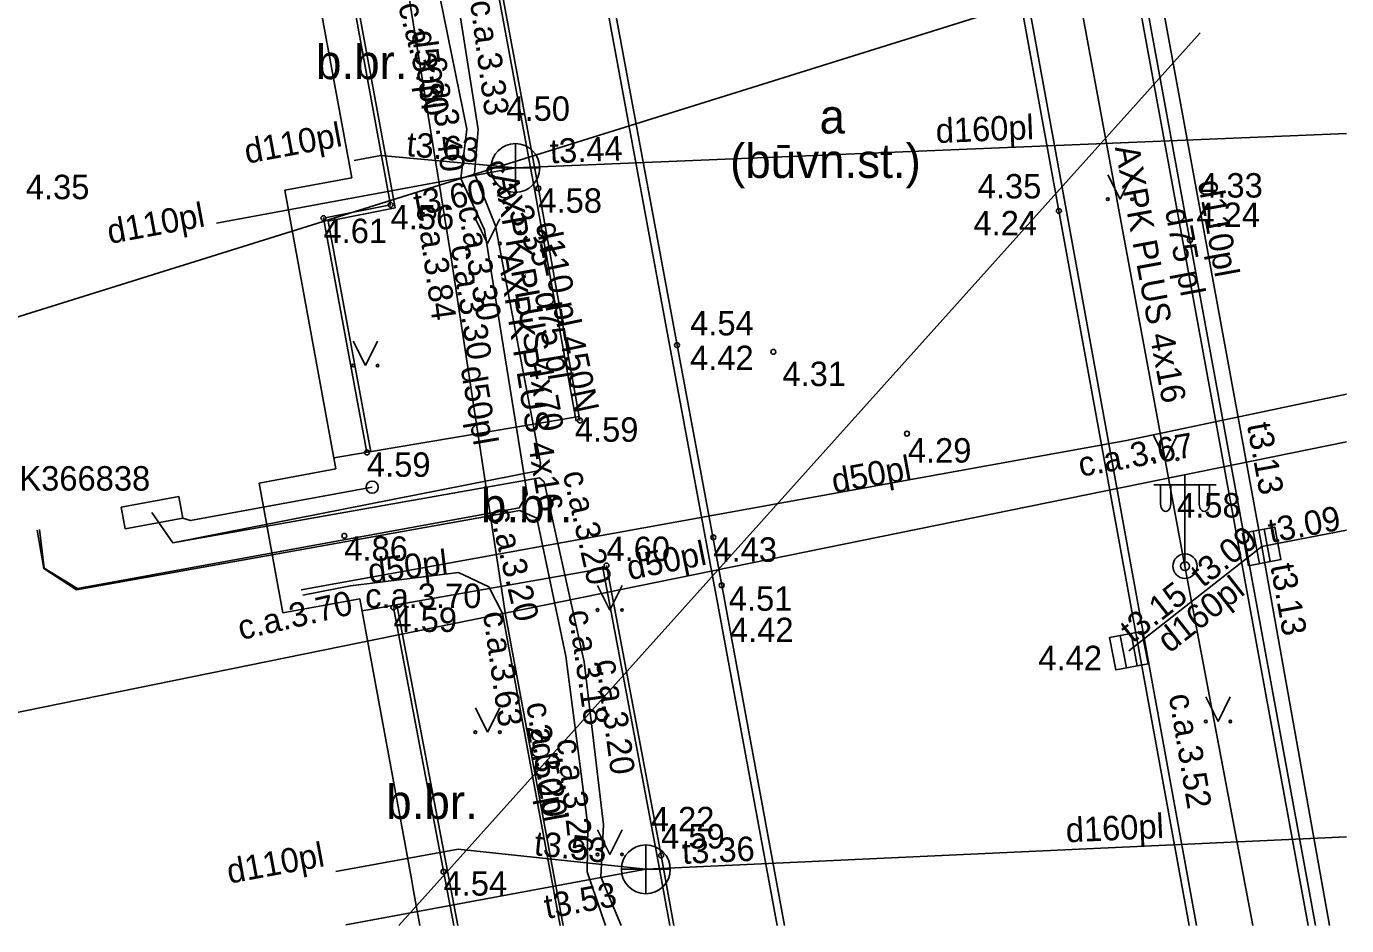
# Model space of a CAD drawing. Extents: x 484635 to 484808, y 278866 to 278977.
# Drawn here: x 484780.57 to 484807.57, y 278866.04 to 278884.44 of the extents above; entities that cross this region are included whole.
import ezdxf

# ---------------------------------------------------------------- set-up
doc = ezdxf.new("R2010")
doc.units = 0
for name, color, linetype in [('APGS_ACRL_####_####_#', 7, 'Continuous'), ('APGS_ACRL_####_TKST_#', 7, 'Continuous'), ('APGS_ELEM_####_####_#', 7, 'Continuous'), ('APGS_ELEM_####_TKST_#', 7, 'Continuous'), ('APGS_VADP_ZSPR_####_I', 7, 'Continuous'), ('APGS_VADP_ZSPR_TKST_I', 7, 'Continuous'), ('BUVE_EKAS_####_####_#', 7, 'Continuous'), ('CELI_CAPM_####_####_#', 7, 'Continuous'), ('CELI_CMAL_####_####_#', 7, 'Continuous'), ('CELI_CSEG_####_TKST_#', 7, 'Continuous'), ('CKOM_ELEM_####_####_#', 7, 'Continuous'), ('CKOM_ZEMJ_####_####_#', 7, 'Continuous'), ('DREN_VADP_####_####_I', 7, 'Continuous'), ('DREN_VADP_####_TKST_I', 7, 'Continuous'), ('ELEK_ACRL_####_####_#', 7, 'Continuous'), ('ELEK_ACRL_####_TKST_#', 7, 'Continuous'), ('ELEK_ELEM_####_####_#', 7, 'Continuous'), ('ELEK_ELEM_####_TKST_#', 7, 'Continuous'), ('ELEK_VADP_ZSPR_####_I', 7, 'Continuous'), ('ELEK_VADP_ZSPR_TKST_I', 7, 'Continuous'), ('LKAN_ELEM_####_####_#', 7, 'Continuous'), ('LKAN_ELEM_PAST_TKST_#', 7, 'Continuous'), ('LKAN_VADP_PAST_####_I', 7, 'Continuous'), ('LKAN_VADP_PAST_TKST_I', 7, 'Continuous'), ('RELJ_AATZ_####_TKST_#', 7, 'Continuous'), ('RELJ_ELEM_####_####_#', 7, 'Continuous'), ('SAKK_KKAN_####_####_I', 7, 'Continuous'), ('SAKK_KKAN_####_TKST_I', 7, 'Continuous'), ('SAKT_VADP_NEDR_####_#', 7, 'Continuous'), ('SKAN_ELEM_####_####_#', 7, 'Continuous'), ('SKAN_ELEM_PAST_TKST_#', 7, 'Continuous'), ('SKAN_VADP_NEDR_####_#', 7, 'Continuous'), ('SKAN_VADP_PAST_####_I', 7, 'Continuous'), ('SKAN_VADP_PAST_TKST_I', 7, 'Continuous'), ('TERT_ELEM_####_####_#', 7, 'Continuous'), ('UDTK_VADP_UDEN_####_I', 7, 'Continuous'), ('UDTK_VADP_UDEN_TKST_I', 7, 'Continuous')]:
    doc.layers.add(name, color=color, linetype=linetype)

msp = doc.modelspace()

# ---------------------------------------------------------------- linework, layer by layer
at = {"layer": 'APGS_ACRL_####_####_#'}
msp.add_lwpolyline([(484800.949, 278891.291), (484804.267, 278873.397), (484805.658, 278866.043)], dxfattribs=at)
at = {"layer": 'APGS_ELEM_####_####_#'}
for p, q in [((484804.267, 278873.397), (484804.267, 278875.28)), ((484804.267, 278875.064), (484803.632, 278875.059)), ((484803.767, 278875.06), (484803.767, 278874.668)), ((484803.977, 278875.062), (484803.977, 278874.668)), ((484804.267, 278875.064), (484804.902, 278875.059)), ((484804.557, 278875.062), (484804.557, 278874.668)), ((484804.767, 278875.06), (484804.767, 278874.668))]:
    msp.add_line(p, q, dxfattribs=at)
for radius in [0.25, 0.09]:
    msp.add_circle((484804.267, 278873.397), radius, dxfattribs=at)
for centre, major_axis, start_param, end_param in [((484803.872, 278874.668), (0, 0.151), 1.570796, 4.712389), ((484804.662, 278874.668), (0, -0.151), 4.712389, 7.853982)]:
    msp.add_ellipse(centre, major_axis=major_axis, ratio=0.695971, start_param=start_param, end_param=end_param, dxfattribs=at)
at = {"layer": 'APGS_VADP_ZSPR_####_I'}
msp.add_lwpolyline([(484800.949, 278891.291), (484804.267, 278873.397), (484805.658, 278866.043)], dxfattribs=at)
at = {"layer": 'BUVE_EKAS_####_####_#'}
for p, q in [((484787.226, 278881.344), (484786.113, 278887.392)), ((484785.849, 278881.09), (484787.226, 278881.344)), ((484785.849, 278881.09), (484786.898, 278875.386)), ((484785.325, 278875.097), (484786.898, 278875.386)), ((484785.813, 278872.441), (484785.325, 278875.097)), ((484787.387, 278872.731), (484785.813, 278872.441)), ((484787.387, 278872.731), (484788.441, 278867.002)), ((484788.486, 278866.756), (484788.441, 278867.002)), ((484788.486, 278866.756), (484788.617, 278866.043))]:
    msp.add_line(p, q, dxfattribs=at)
at = {"layer": 'CELI_CAPM_####_####_#'}
for p, q in [((484793.728, 278877.892), (484792.044, 278886.997)), ((484793.875, 278877.919), (484792.191, 278887.024)), ((484794.641, 278872.977), (484793.728, 278877.891)), ((484794.789, 278873.005), (484793.875, 278877.919)), ((484796.077, 278866.043), (484794.789, 278873.005)), ((484795.925, 278866.043), (484794.641, 278872.978))]:
    msp.add_line(p, q, dxfattribs=at)
for points in [[(484806.787, 278866.043), (484804.221, 278880.039), (484801.029, 278897.438)], [(484806.939, 278866.043), (484804.369, 278880.066), (484801.177, 278897.465)], [(484798.696, 278897.09), (484801.688, 278880.665), (484804.352, 278866.043)], [(484798.844, 278897.117), (484801.835, 278880.691), (484804.505, 278866.043)], [(484789.731, 278887.748), (484790.96, 278881.112), (484791.811, 278876.364)], [(484789.809, 278887.762), (484791.039, 278881.126), (484791.89, 278876.378)], [(484786.839, 278887.208), (484788.016, 278880.789), (484786.643, 278880.516), (484787.532, 278875.724)], [(484786.919, 278887.216), (484788.109, 278880.725), (484786.736, 278880.453), (484787.611, 278875.738)], [(484792.353, 278873.395), (484793.472, 278867.462), (484793.727, 278866.043)], [(484792.432, 278873.41), (484793.55, 278867.477), (484793.808, 278866.043)], [(484789.308, 278866.043), (484788.074, 278872.551)], [(484789.389, 278866.043), (484788.144, 278872.607)]]:
    msp.add_lwpolyline(points, dxfattribs=at)
at = {"layer": 'CELI_CMAL_####_####_#'}
for points in [[(484786.857, 278875.612), (484791.875, 278876.458)], [(484787.433, 278872.482), (484792.441, 278873.362)]]:
    msp.add_lwpolyline(points, dxfattribs=at)
at = {"layer": 'CKOM_ELEM_####_####_#'}
msp.add_circle((484787.638, 278875.013), 0.125, dxfattribs=at)
at = {"layer": 'CKOM_ZEMJ_####_####_#'}
msp.add_lwpolyline([(484783.763, 278874.38), (484783.925, 278874.33), (484787.638, 278875.013)], dxfattribs=at)
at = {"layer": 'DREN_VADP_####_####_I'}
for points in [[(484805.836, 278873.802), (484802.968, 278889.456)], [(484807.226, 278866.043), (484805.836, 278873.802)]]:
    msp.add_lwpolyline(points, dxfattribs=at)
at = {"layer": 'ELEK_ACRL_####_####_#'}
for points in [[(484782.967, 278889.326), (484783.337, 278888.722), (484788.452, 278889.478), (484789.367, 278885.14), (484789.804, 278882.334), (484789.731, 278881.43), (484790.16, 278880.357), (484791.085, 278875.503), (484791.062, 278875.354), (484783.559, 278873.877), (484783.132, 278874.493)], [(484781.185, 278888.845), (484781.329, 278888.091), (484781.841, 278887.878), (484786.673, 278888.772), (484788.257, 278888.812), (484789.576, 278882.339), (484789.452, 278881.33), (484789.936, 278880.279), (484790.808, 278874.869), (484790.648, 278874.587), (484781.611, 278872.941), (484780.931, 278873.356), (484780.833, 278874.148)], [(484783.132, 278874.493), (484783.559, 278873.877), (484791.062, 278875.206), (484791.16, 278875.122), (484791.974, 278871.437), (484792.371, 278868.102), (484792.32, 278867.041), (484792.736, 278866.043)], [(484780.786, 278874.134), (484780.92, 278873.348), (484781.587, 278872.91), (484790.66, 278874.534), (484791.005, 278874.377), (484791.603, 278871.553), (484792.054, 278868.088), (484792.037, 278867.141), (484792.413, 278866.043)]]:
    msp.add_lwpolyline(points, dxfattribs=at)
at = {"layer": 'ELEK_ELEM_####_####_#'}
msp.add_lwpolyline([(484782.502, 278874.606), (484783.682, 278874.822), (484783.763, 278874.38), (484782.583, 278874.163)], close=True, dxfattribs=at)
at = {"layer": 'ELEK_VADP_ZSPR_####_I'}
for points in [[(484782.967, 278889.326), (484783.337, 278888.722), (484788.452, 278889.478), (484789.367, 278885.14), (484789.804, 278882.334), (484789.731, 278881.43), (484790.16, 278880.357), (484791.085, 278875.503), (484791.062, 278875.354), (484783.559, 278873.877), (484783.132, 278874.493)], [(484781.185, 278888.845), (484781.329, 278888.091), (484781.841, 278887.878), (484786.673, 278888.772), (484788.257, 278888.812), (484789.576, 278882.339), (484789.452, 278881.33), (484789.936, 278880.279), (484790.808, 278874.869), (484790.648, 278874.587), (484781.611, 278872.941), (484780.931, 278873.356), (484780.833, 278874.148)], [(484783.132, 278874.493), (484783.559, 278873.877), (484791.062, 278875.206), (484791.16, 278875.122), (484791.974, 278871.437), (484792.371, 278868.102), (484792.32, 278867.041), (484792.736, 278866.043)], [(484780.786, 278874.134), (484780.92, 278873.348), (484781.587, 278872.91), (484790.66, 278874.534), (484791.005, 278874.377), (484791.603, 278871.553), (484792.054, 278868.088), (484792.037, 278867.141), (484792.413, 278866.043)]]:
    msp.add_lwpolyline(points, dxfattribs=at)
at = {"layer": 'LKAN_ELEM_####_####_#'}
for p, q in [((484805.663, 278874.112), (484805.789, 278873.449)), ((484805.884, 278874.155), (484806.01, 278873.491)), ((484802.944, 278871.978), (484803.07, 278871.315)), ((484803.165, 278872.02), (484803.291, 278871.357))]:
    msp.add_line(p, q, dxfattribs=at)
for points in [[(484805.442, 278874.07), (484806.105, 278874.197), (484806.231, 278873.533), (484805.568, 278873.407)], [(484802.723, 278871.936), (484803.386, 278872.062), (484803.512, 278871.399), (484802.849, 278871.273)]]:
    msp.add_lwpolyline(points, close=True, dxfattribs=at)
at = {"layer": 'LKAN_VADP_PAST_####_I'}
for points in [[(484805.836, 278873.802), (484807.573, 278874.132)], [(484803.117, 278871.667), (484805.836, 278873.802)]]:
    msp.add_lwpolyline(points, dxfattribs=at)
at = {"layer": 'RELJ_ELEM_####_####_#'}
for centre in [(484791.039, 278881.126), (484788.016, 278880.789), (484786.643, 278880.516), (484801.688, 278880.665), (484804.369, 278880.066), (484793.875, 278877.919), (484795.846, 278877.781), (484791.89, 278876.378), (484798.579, 278876.108), (484787.532, 278875.724), (484787.069, 278874.017), (484794.619, 278873.986), (484792.432, 278873.41), (484794.789, 278873.005), (484788.074, 278872.551), (484793.55, 278867.477), (484789.099, 278867.147)]:
    msp.add_circle(centre, 0.05, dxfattribs=at)
at = {"layer": 'SAKK_KKAN_####_####_I'}
for points in [[(484784.69, 278887.431), (484786.281, 278887.759), (484787.215, 278887.727), (484787.779, 278887.388), (484788.143, 278886.589), (484789.238, 278879.793), (484790.369, 278872.4), (484791.546, 278866.043)], [(484807.573, 278876.913), (484803.072, 278875.969), (484786.187, 278872.916)], [(484786.222, 278872.805), (484787.195, 278872.997), (484789.405, 278873.268), (484790.029, 278872.975), (484790.303, 278872.431), (484791.483, 278866.043)]]:
    msp.add_lwpolyline(points, dxfattribs=at)
at = {"layer": 'SAKT_VADP_NEDR_####_#'}
msp.add_line((484788.185, 278866.043), (484804.576, 278884.31), dxfattribs=at)
at = {"layer": 'SKAN_ELEM_####_####_#'}
for p, q in [((484790.568, 278881.044), (484790.568, 278882.044)), ((484790.068, 278881.544), (484791.068, 278881.544)), ((484793.237, 278866.695), (484793.237, 278867.695)), ((484792.737, 278867.195), (484793.737, 278867.195))]:
    msp.add_line(p, q, dxfattribs=at)
for centre in [(484790.568, 278881.544), (484793.237, 278867.195)]:
    msp.add_circle(centre, 0.5, dxfattribs=at)
at = {"layer": 'SKAN_VADP_NEDR_####_#'}
msp.add_lwpolyline([(484756.132, 278870.921), (484807.573, 278886.997)], dxfattribs=at)
at = {"layer": 'SKAN_VADP_PAST_####_I'}
for p, q in [((484784.455, 278880.413), (484790.568, 278881.544)), ((484786.898, 278867.149), (484789.396, 278867.61)), ((484789.396, 278867.61), (484793.237, 278867.195)), ((484787.099, 278866.056), (484793.237, 278867.195))]:
    msp.add_line(p, q, dxfattribs=at)
for points in [[(484790.568, 278881.544), (484807.573, 278882.25)], [(484790.568, 278881.544), (484787.815, 278881.799), (484787.268, 278881.698)], [(484793.237, 278867.195), (484807.573, 278867.859)]]:
    msp.add_lwpolyline(points, dxfattribs=at)
at = {"layer": 'TERT_ELEM_####_####_#'}
for p, q in [((484802.688, 278881.403), (484802.938, 278880.903)), ((484802.938, 278880.903), (484803.188, 278881.403)), ((484789.75, 278880.5), (484790, 278880)), ((484790, 278880), (484790.25, 278880.5)), ((484787.25, 278878), (484787.5, 278877.5)), ((484787.5, 278877.5), (484787.75, 278878)), ((484803.616, 278876.086), (484803.866, 278875.586)), ((484803.866, 278875.586), (484804.116, 278876.086)), ((484792.25, 278873), (484792.5, 278872.5)), ((484792.5, 278872.5), (484792.75, 278873)), ((484804.694, 278870.721), (484804.944, 278870.221)), ((484804.944, 278870.221), (484805.194, 278870.721)), ((484789.75, 278870.5), (484790, 278870)), ((484790, 278870), (484790.25, 278870.5)), ((484792.25, 278868), (484792.5, 278867.5)), ((484792.5, 278867.5), (484792.75, 278868))]:
    msp.add_line(p, q, dxfattribs=at)
for centre, radius in [((484802.688, 278880.903), 0.028), ((484803.188, 278880.903), 0.0263), ((484789.75, 278880), 0.028), ((484790.25, 278880), 0.0263), ((484787.25, 278877.5), 0.028), ((484787.75, 278877.5), 0.0263), ((484803.615, 278875.585), 0.028), ((484804.115, 278875.585), 0.0263), ((484792.25, 278872.5), 0.028), ((484792.75, 278872.5), 0.0263), ((484789.75, 278870), 0.028), ((484790.25, 278870), 0.0263), ((484804.694, 278870.22), 0.028), ((484805.194, 278870.22), 0.0263), ((484792.25, 278867.5), 0.028), ((484792.75, 278867.5), 0.0263)]:
    msp.add_circle(centre, radius, dxfattribs=at)
at = {"layer": 'UDTK_VADP_UDEN_####_I'}
msp.add_lwpolyline([(484807.573, 278875.943), (484775.943, 278869.5)], dxfattribs=at)

# ---------------------------------------------------------------- texts
at = {"layer": 'APGS_ACRL_####_TKST_#'}
msp.add_text('d75 pl', height=0.5, rotation=280.5048, dxfattribs=at).set_placement((484803.858, 278880.682))
at = {"layer": 'APGS_ELEM_####_TKST_#'}
msp.add_text('c.a.3.52', height=0.5, rotation=279.4578, dxfattribs=at).set_placement((484803.934, 278870.751))
at = {"layer": 'APGS_VADP_ZSPR_TKST_I'}
msp.add_text('AXPK PLUS 4x16', height=0.5, rotation=280.5048, dxfattribs=at).set_placement((484802.831, 278881.965))
at = {"layer": 'CELI_CSEG_####_TKST_#'}
for s, p in [('b.br.', (484786.49, 278883.361)), ('a', (484796.791, 278882.249)), ('(būvn.st.)', (484794.961, 278881.339)), ('b.br.', (484789.864, 278874.291)), ('b.br.', (484787.927, 278868.224))]:
    msp.add_text(s, height=0.7, dxfattribs=at).set_placement(p)
at = {"layer": 'DREN_VADP_####_TKST_I'}
for s, rotation, p in [('d110pl', 280.3837, (484804.528, 278881.257)), ('t3.13', 280.3837, (484805.533, 278876.289)), ('t3.13', 280.1533, (484806.013, 278873.406))]:
    msp.add_text(s, height=0.5, rotation=rotation, dxfattribs=at).set_placement(p)
at = {"layer": 'ELEK_ACRL_####_TKST_#'}
for s, rotation, p in [('c.a.3.30', 284.2745, (484788.165, 278884.87)), ('c.a.3.33', 277.4256, (484789.641, 278884.947)), ('c.a.3.40', 276.7045, (484788.769, 278883.802)), ('c.a.3.35', 297.5007, (484789.912, 278881.581)), ('c.a.3.30', 279.7748, (484789.392, 278880.728)), ('d110 pl 450N', 281.9085, (484790.98, 278880.394)), ('c.a.3.30', 278.5267, (484789.243, 278879.94)), ('d75 pl', 279.1513, (484790.961, 278878.98)), ('c.a.3.20', 282.7944, (484791.534, 278875.295)), ('c.a.3.20', 283.2702, (484790.029, 278874.541)), ('c.a.3.18', 278.272, (484791.647, 278872.47)), ('c.a.3.20', 277.49, (484792.216, 278871.465)), ('c.a.3.20', 278.6233, (484790.79, 278870.583)), ('c.a.3.26', 276.4365, (484791.412, 278869.846))]:
    msp.add_text(s, height=0.5, rotation=rotation, dxfattribs=at).set_placement(p)
at = {"layer": 'ELEK_ELEM_####_TKST_#'}
msp.add_text('K366838', height=0.5, dxfattribs=at).set_placement((484780.421, 278874.943))
at = {"layer": 'ELEK_VADP_ZSPR_TKST_I'}
for s, rotation, p in [('AXPK PLUS 4x70', 280.2236, (484790.127, 278881.387)), ('AXPK PLUS 4x16', 279.1513, (484790.206, 278879.767))]:
    msp.add_text(s, height=0.5, rotation=rotation, dxfattribs=at).set_placement(p)
at = {"layer": 'LKAN_ELEM_PAST_TKST_#'}
for s, p in [('4.58', (484804.104, 278874.392)), ('4.42', (484801.268, 278871.269))]:
    msp.add_text(s, height=0.5, dxfattribs=at).set_placement(p)
at = {"layer": 'LKAN_VADP_PAST_TKST_I'}
for s, rotation, p in [('t3.09', 10.7692, (484806.021, 278873.869)), ('t3.09', 38.1355, (484804.631, 278872.945)), ('t3.15', 38.1355, (484803.191, 278871.804)), ('d160pl', 38.1355, (484803.948, 278871.602))]:
    msp.add_text(s, height=0.5, rotation=rotation, dxfattribs=at).set_placement(p)
at = {"layer": 'RELJ_AATZ_####_TKST_#'}
for s, p in [(' 4.35', (484780.367, 278880.905)), ('4.35', (484800.027, 278880.92)), ('4.33', (484804.557, 278880.938)), ('4.58', (484791.039, 278880.626)), ('4.24', (484804.5, 278880.337)), ('4.56', (484788.016, 278880.289)), ('4.24', (484799.94, 278880.165)), ('4.61', (484786.643, 278880.007)), ('4.54', (484794.144, 278878.118)), ('4.42', (484794.142, 278877.408)), (' 4.31', (484795.846, 278877.081)), ('4.59', (484791.785, 278875.942)), ('4.29', (484798.597, 278875.516)), ('4.59', (484787.532, 278875.225)), ('4.86', (484787.069, 278873.506)), ('4.60', (484792.432, 278873.501)), ('4.43', (484794.619, 278873.486)), ('4.51', (484794.934, 278872.485)), ('4.59', (484788.074, 278872.051)), ('4.42', (484794.958, 278871.843)), ('4.59', (484793.55, 278867.62)), ('4.54', (484789.099, 278866.656))]:
    msp.add_text(s, height=0.5, dxfattribs=at).set_placement(p)
at = {"layer": 'SAKK_KKAN_####_TKST_I'}
for s, rotation, p in [('d50pl', 277.6149, (484788.444, 278884.334)), ('c.a.3.84', 277.9909, (484788.539, 278880.755)), ('d50pl', 279.6646, (484789.447, 278877.455)), ('c.a.3.67', 10.1216, (484802.132, 278875.224)), ('d50pl', 10.2483, (484797.087, 278874.887)), ('d50pl', 6.991, (484787.585, 278873.045)), ('c.a.3.70', 13.0053, (484784.955, 278871.883)), ('c.a.3.63', 277.9301, (484789.904, 278872.443)), ('2d50pl', 280.4911, (484790.792, 278870.114))]:
    msp.add_text(s, height=0.5, rotation=rotation, dxfattribs=at).set_placement(p)
msp.add_text('c.a.3.70', height=0.5, dxfattribs=at).set_placement((484787.495, 278872.541))
at = {"layer": 'SKAN_ELEM_PAST_TKST_#'}
for s, p in [('4.50', (484790.384, 278882.508)), ('4.22', (484793.339, 278867.972))]:
    msp.add_text(s, height=0.5, dxfattribs=at).set_placement(p)
at = {"layer": 'SKAN_VADP_PAST_TKST_I'}
for s, rotation, p in [('d110pl', 10.4853, (484785.075, 278881.629)), ('d160pl', 2.375, (484799.178, 278882.052)), ('t3.63', 354.7058, (484788.326, 278881.79)), ('t3.44', 2.375, (484791.285, 278881.638)), ('t3.60', 10.487, (484788.54, 278880.567)), ('d110pl', 10.487, (484782.268, 278879.988)), ('d160pl', 2.6533, (484801.839, 278867.744)), ('t3.53', 353.8312, (484790.935, 278867.486)), ('t3.36', 2.6533, (484793.989, 278867.303)), ('d110pl', 10.4559, (484784.716, 278866.899)), ('t3.53', 10.5052, (484791.21, 278866.177))]:
    msp.add_text(s, height=0.5, rotation=rotation, dxfattribs=at).set_placement(p)
at = {"layer": 'UDTK_VADP_UDEN_TKST_I'}
msp.add_text('d50pl', height=0.5, rotation=11.5123, dxfattribs=at).set_placement((484792.903, 278873.108))

doc.saveas('drawing.dxf')
